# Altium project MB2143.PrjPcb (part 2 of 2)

## Sheet Arduino.SchDoc: Arduino
size A4; Date: Not used; ApprovedBy: Not used; CheckedBy: Not used; Author: Not used; CompanyName: STMicroelectronics; DrawnBy: Not used; Engineer: Not used; Organization: Not used; Address1: Not used; Address2: Not used; Address3: Not used; Address4: Not used; DocumentNumber: Not used; Revision: Not used; SheetNumber: 6; SheetTotal: 11
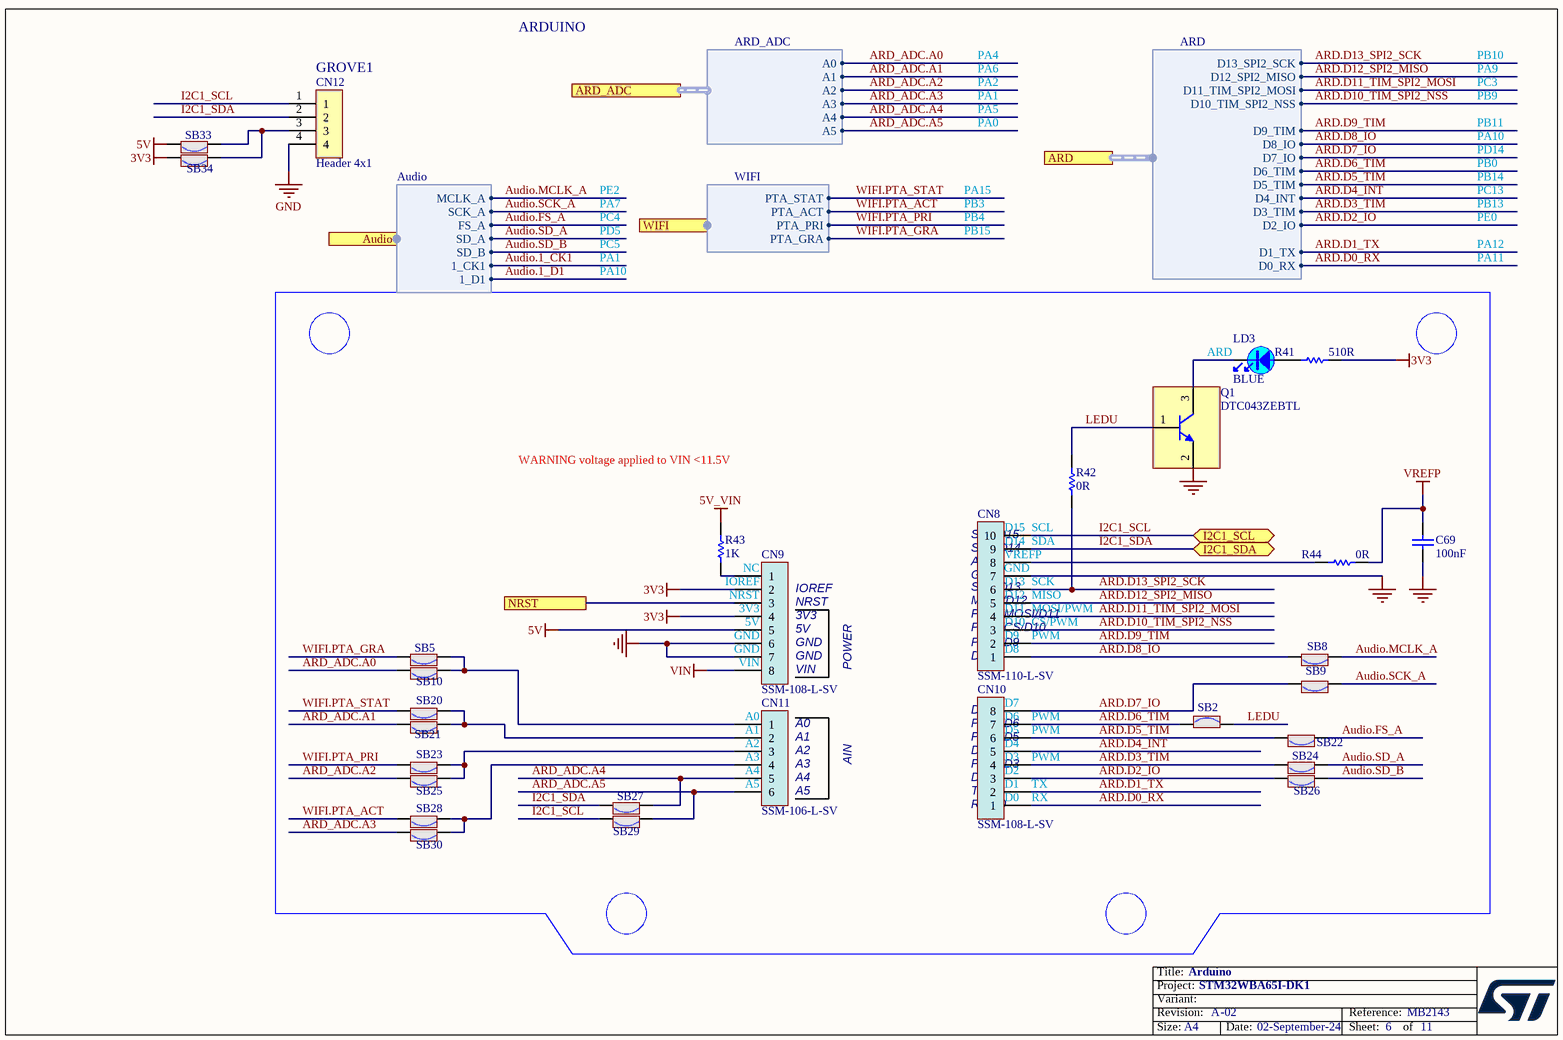
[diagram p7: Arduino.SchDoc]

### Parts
C69  value 100nF  [C0402]
CN8  value SSM-110-L-SV  [CON_SAMTEC_SSM-110-L-SV]  (hidden comment: Socket 10x1)
CN9  value SSM-108-L-SV  [CON_SAMTEC_SSM-108-L-SV]  (hidden comment: Socket 8x1)
CN10  value SSM-108-L-SV  [CON_SAMTEC_SSM-108-L-SV]  (hidden comment: Socket 8x1)
CN11  value SSM-106-L-SV  [CON_SAMTEC_SSM-106-L-SV]  (hidden comment: Socket 6x1)
CN12  Header 4x1  [CON_988-JIUBABA_A2006LF-04A]
LD3  value BLUE  [LED_0603_VISHAY_VLMB1300-GS08_BLUE_1A2K_H0P8]  (hidden comment: LED_blue)
Q1  DTC043ZEBTL  [NPN_SOT416-FL_EMT3F_1616_SC89]
R41  value 510R  [R0402]  (hidden comment: Resistor)
R42  value 0R  [R0402]
R43  value 1K  [R0402]  (hidden comment: Resistor)
R44  value 0R  [R0402]
SB2  (no value)  [SOLDER-BRIDGE_R0603-0R]
SB5  (no value)  [SOLDER-BRIDGE_R0603-0R]
SB8  (no value)  [SOLDER-BRIDGE_R0603-0R]
SB9  (no value)  [SOLDER-BRIDGE_R0603-0R]
SB10  (no value)  [SOLDER-BRIDGE_R0603-0R]
SB20  (no value)  [SOLDER-BRIDGE_R0603-0R]
SB21  (no value)  [SOLDER-BRIDGE_R0603-0R]
SB22  (no value)  [SOLDER-BRIDGE_R0603-0R]
SB23  (no value)  [SOLDER-BRIDGE_R0603-0R]
SB24  (no value)  [SOLDER-BRIDGE_R0603-0R]
SB25  (no value)  [SOLDER-BRIDGE_R0603-0R]
SB26  (no value)  [SOLDER-BRIDGE_R0603-0R]
SB27  (no value)  [SOLDER-BRIDGE_R0603-0R]
SB28  (no value)  [SOLDER-BRIDGE_R0603-0R]
SB29  (no value)  [SOLDER-BRIDGE_R0603-0R]
SB30  (no value)  [SOLDER-BRIDGE_R0603-0R]
SB33  (no value)  [SOLDER-BRIDGE_R0603-0R]
SB34  (no value)  [SOLDER-BRIDGE_R0603-0R]

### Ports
ARD (harness ARD), ARD_ADC (harness ARD_ADC), Audio (harness Audio), I2C1_SCL (bidir), I2C1_SDA (bidir), NRST, WIFI (harness WIFI)

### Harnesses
WIFI: PTA_STAT, PTA_ACT, PTA_PRI, PTA_GRA
Audio: MCLK_A, 1_CK1, FS_A, SD_A, SCK_A, SD_B, 1_D1
ARD_ADC: A0, A1, A2, A3, A4, A5
ARD: D0_RX, D1_TX, D2_IO, D3_TIM, D4_INT, D5_TIM, D6_TIM, D7_IO, D8_IO, D9_TIM, D10_TIM_SPI2_NSS, D11_TIM_SPI2_MOSI, D12_SPI2_MISO, D13_SPI2_SCK

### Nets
3V3: CN9.2 CN9.4 R41.1 SB34.2
5V: CN9.5 SB33.2
5V_VIN: R43.2
GND: C69.2 CN8.7 CN9.6 CN9.7 CN12.4 Q1.2(E)
VIN: CN9.8
VREFP: C69.1 R44.2  [project net VBAT]
ARD.D0_RX: CN10.1 ; port ARD.D0_RX
ARD.D1_TX: CN10.2 ; port ARD.D1_TX
ARD.D2_IO: CN10.3 SB26.2 ; port ARD.D2_IO
ARD.D3_TIM: CN10.4 SB24.2 ; port ARD.D3_TIM
ARD.D4_INT: CN10.5 ; port ARD.D4_INT
ARD.D5_TIM: CN10.6 SB22.2 ; port ARD.D5_TIM
ARD.D6_TIM: CN10.7 SB2.1 ; port ARD.D6_TIM
ARD.D7_IO: CN10.8 SB9.2 ; port ARD.D7_IO
ARD.D8_IO: CN8.1 SB8.2 ; port Audio.1_D1, port ARD.D8_IO  [also labelled Audio.1_D1]
ARD.D9_TIM: CN8.2 ; port ARD.D9_TIM
ARD.D10_TIM_SPI2_NSS: CN8.3 ; port ARD.D10_TIM_SPI2_NSS
ARD.D11_TIM_SPI2_MOSI: CN8.4 ; port ARD.D11_TIM_SPI2_MOSI
ARD.D12_SPI2_MISO: CN8.5 ; port ARD.D12_SPI2_MISO
ARD.D13_SPI2_SCK: CN8.6 R42.1 ; port ARD.D13_SPI2_SCK
ARD_ADC.A0: SB10.2 ; port ARD_ADC.A0
ARD_ADC.A1: SB21.2 ; port ARD_ADC.A1
ARD_ADC.A2: SB25.2 ; port ARD_ADC.A2
ARD_ADC.A3: SB30.2 ; port Audio.1_CK1, port ARD_ADC.A3  [also labelled Audio.1_CK1]
ARD_ADC.A4: CN11.5 SB27.1 ; port ARD_ADC.A4
ARD_ADC.A5: CN11.6 SB29.1 ; port ARD_ADC.A5
Audio.FS_A: SB22.1 ; port Audio.FS_A
Audio.MCLK_A: SB8.1 ; port Audio.MCLK_A
Audio.SCK_A: SB9.1 ; port Audio.SCK_A
Audio.SD_A: SB24.1 ; port Audio.SD_A
Audio.SD_B: SB26.1 ; port Audio.SD_B
I2C1_SCL: CN8.10 CN12.1 SB29.2 ; port I2C1_SCL
I2C1_SDA: CN8.9 CN12.2 SB27.2 ; port I2C1_SDA
LEDU: Q1.1(B) R42.2 SB2.2
NRST: CN9.3 ; port NRST
WIFI.PTA_ACT: SB28.2 ; port WIFI.PTA_ACT  [project net MCU.SWO]
WIFI.PTA_GRA: SB5.2 ; port WIFI.PTA_GRA
WIFI.PTA_PRI: SB23.2 ; port WIFI.PTA_PRI
WIFI.PTA_STAT: SB20.2 ; port WIFI.PTA_STAT
NetCN8_8: CN8.8 R44.1
NetCN9_1: CN9.1 R43.1
NetCN11_1: CN11.1 SB5.1 SB10.1
NetCN11_2: CN11.2 SB20.1 SB21.1
NetCN11_3: CN11.3 SB23.1 SB25.1
NetCN11_4: CN11.4 SB28.1 SB30.1
NetCN12_3: CN12.3 SB33.1 SB34.1
NetLD3_1: LD3.1 R41.2
NetLD3_2: LD3.2 Q1.3(C)

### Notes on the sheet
- ARDUINO
- (near CN12) GROVE1
- PA4
- PA6
- PA1
- PA2
- PA5
- PB9
- PB10
- PA9
- PC3
- PA0
- PA10
- PD14
- PB0
- PB11
- PB14
- PC5
- PC4
- PD5
- PE2
- PA7
- PA15
- PB4
- PB3
- PB15
- PC13
- PB13
- PE0
- PA12
- PA11
- (near LD3) ARD
- WARNING voltage applied to VIN <11.5V
- (near CN9) NC
- (near CN9) IOREF
- (near CN8) SDA/D14
- (near CN8) SCL/D15
- (near CN8) SCK/D13
- (near CN8) AVDD
- (near CN8) GND
- (near CN8) VREFP
- (near CN8) D13
- (near CN8) D14
- (near CN8) D15
- SCL
- (near CN8) SDA
- (near CN8) SCK
- (near CN9) NRST
- (near CN9) 3V3
- (near CN9) 5V
- (near CN9) GND
- (near CN8) D8
- (near CN8) PWM/D9
- (near CN8) PWM/CS/D10
- (near CN8) MISO/D12
- (near CN8) PWM/MOSI/D11
- (near CN8) D9
- (near CN8) D10
- (near CN8) D11
- (near CN8) D12
- (near CN8) MISO
- (near CN8) MOSI/PWM
- (near CN8) CS/PWM
- (near CN8) PWM
- (near CN9) VIN
- (near CN11) A0
- POWER
- (near CN10) D7
- (near CN10) D6
- (near CN10) PWM
- (near CN11) A1
- (near CN11) A2
- (near CN11) A3
- (near CN11) A4
- (near CN11) A5
- AIN
- (near CN10) TX/D1
- (near CN10) D2
- (near CN10) D4
- (near CN10) PWM/D3
- (near CN10) PWM/D5
- (near CN10) PWM/D6
- (near CN10) D5
- (near CN10) D3
- (near CN10) D1
- (near CN10) TX
- (near CN10) RX/D0
- (near CN10) D0
- (near CN10) RX

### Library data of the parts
C69 = MCD-00006: Capacitor,100nF,16V,X7R,10%,0402; Manufacturer_Part_Number: CC0402KRX7R7BB104; Manufacturer: YAGEO; Provided_By: Subcon; Initial_Board_Reference: mb1274
CN8 = MCD-02342: Socket, 10x1, 2.54mm, VR, SMT, Height 7.37mm; Part_Type: Connector; Part_Preference: Recommended; Manufacturer: SAMTEC; Order_Code_RS: 765-5420
CN9 CN10 = MCD-02345: Socket, 8x1, 2.54mm, VR, SMT, Height 7.37mm; Part_Type: Connector; Part_Preference: Recommended; Manufacturer: SAMTEC; Order_Code_RS: 765-5411
CN11 = MCD-02346: Socket, 6x1, 2.54mm, VR, SMT, Height 7.37mm; Part_Type: Connector; Part_Preference: Recommended; Manufacturer: SAMTEC; Order_Code_RS: 765-5408
CN12 = MCD-03083: GROVE female header, SMD, 4 POS, 2.0mm; Part_Type: Connector; Part_Preference: Recommended; Manufacturer: SEEED TECHNOLOGY; Manufacturer_Part_Number: 114020161; Partial_Alternate_Internal_Part_Number: MCD-01741; Order_Code_RS: NA; ShowFields: YES; ID: 5199
LD3 = MCD-00584: LED Blue, 0603 SMD, 3.3 V Forward Voltage; Part_Type: Display; Part_Preference: Recommended; Manufacturer: VISHAY; Manufacturer_Part_Number: VLMB1300-GS08; Order_Code_RS: 7730430; Component_Country_Of_Origin: China; ShowFields: YES; ID: 3160
Q1 = MCD-00280: Buffer transistor; Part_Type: IC; Manufacturer: ROHM; Provided_By: Subcon; Initial_Board_Reference: MB1329
R41 = MCD-00064: Resistor,510R,0402,1%,1/16W; Manufacturer_Part_Number: RC0402FR-07510RL; Manufacturer: YAGEO; Provided_By: Subcon; Initial_Board_Reference: MB1274
R42 R44 = MCD-00052: Resistor,0R,0402,5%,1/16W; Manufacturer_Part_Number: RC0402JR-070RL; Manufacturer: YAGEO; Provided_By: Subcon; Initial_Board_Reference: mb1274
R43 = MCD-00061: Resistor,1K,0402,1%,1/16W; Manufacturer_Part_Number: RC0402FR-071KL; Manufacturer: YAGEO; Provided_By: Subcon; Initial_Board_Reference: mb1274
SB2 SB5 SB8-SB10 SB20-SB30 SB33 SB34 = MCD-00071: Solder Bridge ON; Part_Type: Mechanical; Provided_By: Subcon; Initial_Board_Reference: mb1274

## Sheet USB_Joystick_Reset.SchDoc: MCU CLOCK & RESET
size A4; Date: Not used; ApprovedBy: Not used; CheckedBy: Not used; Author: Not used; CompanyName: STMicroelectronics; DrawnBy: Not used; Engineer: Not used; Organization: Not used; Address1: Not used; Address2: Not used; Address3: Not used; Address4: Not used; DocumentNumber: Not used; Revision: Not used; SheetNumber: 4; SheetTotal: 11
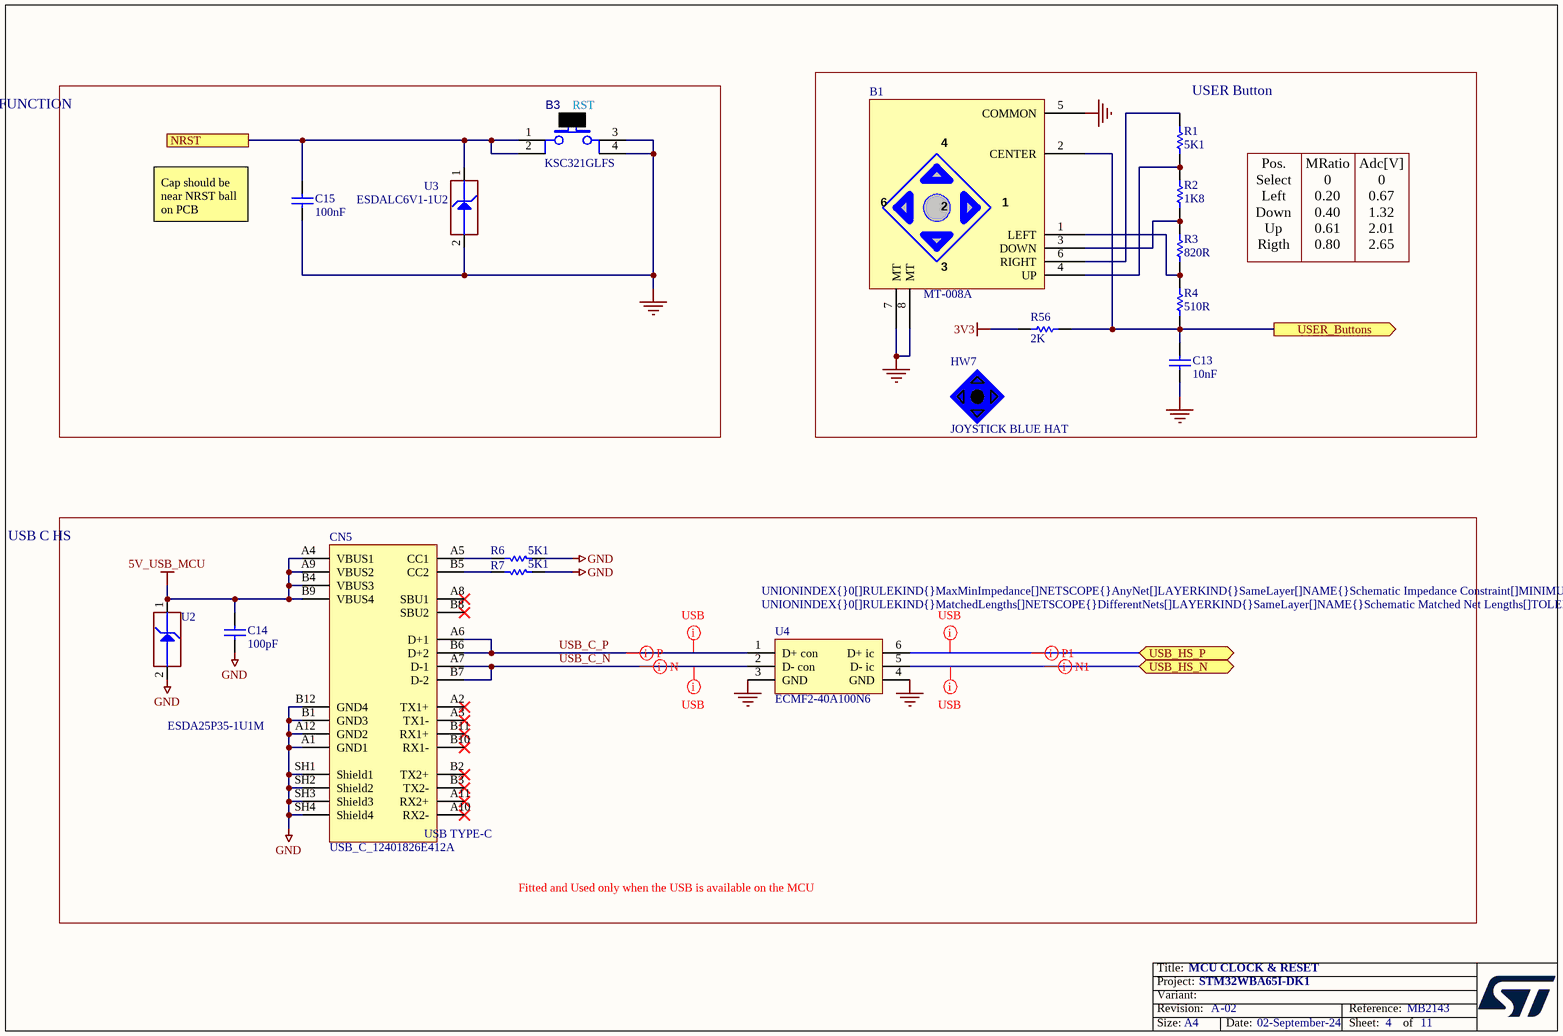
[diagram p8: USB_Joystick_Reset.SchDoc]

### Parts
B1  value MT-008A  [SWI_XIEJIA_MT-008A_6P]  (hidden comment: Joystick MT-008A_M)
B3  value KSC321GLFS  [SWI_C&K_KSC321GLFS_BLACK]  (hidden comment: SW_BLACK_KSC321GLFS)
C13  value 10nF  [C0402]  (hidden comment: Capacitor)
C14  value 100pF  [C0402]  (hidden comment: Capacitor)
C15  value 100nF  [C0402]  (hidden comment: Capacitor)
CN5  value USB_C_12401826E412A  [CON_USB-TYPEC_AMPHENOL_12401826E412A]  (hidden comment: USB_TYPE_C_Receptacle)
HW7  value JOYSTICK BLUE HAT  (hidden comment: JOYSTICK_BLUE_HAT)  (mechanical)
R1  value 5K1  [R0402]  (hidden comment: Resistor)
R2  value 1K8  [R0402]  (hidden comment: Resistor)
R3  value 820R  [R0402]  (hidden comment: Resistor)
R4  value 510R  [R0402]  (hidden comment: Resistor)
R6  value 5K1  [R0402]  (hidden comment: Resistor)
R7  value 5K1  [R0402]  (hidden comment: Resistor)
R56  value 2K  [R0402]  (hidden comment: Resistor)
U2  value ESDA25P35-1U1M  [ESD_QFN1610_2N_1K_2A]  (hidden comment: ESD-TRANSIL)
U3  value ESDALC6V1-1U2  [ESD_ST0201]
U4  ECMF2-40A100N6  [ESD_UQFN-6L_1P45X1P4_P040]

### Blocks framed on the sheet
RESET FUNCTION: B3 C15 U3
USER Button: B1 C13 HW7 R1-R4 R56
USB C HS: C14 CN5 R6 R7 U2 U4

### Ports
NRST, USB_HS_N (bidir), USB_HS_P (bidir), USER_Buttons (out)

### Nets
3V3: R56.1
5V_USB_MCU: C14.2 CN5.A4(VBUS1) CN5.A9(VBUS2) CN5.B4(VBUS3) CN5.B9(VBUS4) U2.1(IO1)
GND: B1.5(COMMON) B1.7(MT) B1.8(MT) B3.3 B3.4 C13.1 C14.1 C15.1 CN5.A1(GND1) CN5.A12(GND2) CN5.B1(GND3) CN5.B12(GND4) CN5.SH1(Shield1) CN5.SH2(Shield2) CN5.SH3(Shield3) CN5.SH4(Shield4) R6.1 R7.1 U2.2(GND) U3.2(GND) U4.3(GND) U4.4(GND)
NRST: B3.1 B3.2 C15.2 U3.1(IO1) ; port NRST
USB_C_N: CN5.A7(D-1) CN5.B7(D-2) U4.2(D-_con)
USB_C_P: CN5.A6(D+1) CN5.B6(D+2) U4.1(D+_con)
USB_HS_N: U4.5(D-_ic) ; port USB_HS_N
USB_HS_P: U4.6(D+_ic) ; port USB_HS_P
NetB1_1: B1.1(LEFT) R3.1 R4.2
NetB1_2: B1.2(CENTER) C13.2 R4.1 R56.2 ; port USER_Buttons
NetB1_3: B1.3(DOWN) R2.1 R3.2
NetB1_4: B1.4(UP) R1.1 R2.2
NetB1_6: B1.6(RIGHT) R1.2
NetCN5_A5: CN5.A5(CC1) R6.2
NetCN5_B5: CN5.B5(CC2) R7.2

Not connected (* = marked no-connect by the designer): CN5 A2(TX1+)* A3(TX1-)* A8(SBU1)* A10(RX2-)* A11(RX2+)* B2(TX2+)* B3(TX2-)* B8(SBU2)* B10(RX1-)* B11(RX1+)*

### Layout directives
rule Undefined; rule Matched Net Lengths [Tolerance = 2mm]; rule Impedance Constraint [Min = 85.00    Max = 95.00    ]: USB_C_N, USB_C_P, USB_HS_N, USB_HS_P
differential pair: USB_C_N, USB_C_P, USB_HS_N, USB_HS_P

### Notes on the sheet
- (near B3) RST
- Cap should be near NRST ball on PCB
- Pos.
  Select
  Left
  Down
  Up
  Rigth
- MRatio
  0
  0.20
  0.40
  0.61
  0.80
- Adc[V]
  0
  0.67
  1.32
  2.01
  2.65
- Fitted and Used only when the USB is available on the MCU

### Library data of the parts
B1 = MCD-00132: Joystick, 4 dir, 1 OK; BMS_Part_Number: 9180124; Part_Preference: Recommended; Part_Type: Misc; Manufacturer: XIEJIA ELECTRONICS
B3 = MCD-00175: Switch HW BLACK High3.5mm 2Newtons; Part_Type: Misc; Manufacturer: C&K; Provided_By: SUBCO; Initial_Board_Reference: MB1274
C13 = MCD-00011: Capacitor, MLCC, 10nF, 16V, X7R, +/-10%, 0402, T=0.5mm; Manufacturer_Part_Number: CC0402KRX7R7BB103; Manufacturer: YAGEO; Part_Preference: Recommended; Provided_By: SUBCO; ECCN_US: EAR99; ECCN_EU: NEC; Order_Code_RS: 669-8688
C14 = MCD-00205: Capacitor, MLCC, 100pF, 50V, NPO, +/-5%, 0402, T=0.5mm; Manufacturer_Part_Number: CC0402JRNPO9BN101; Manufacturer: YAGEO; Part_Preference: Recommended; Component_Country_Of_Origin: China
C15 = MCD-00006: Capacitor, MLCC, 100nF, 16V, X7R, 10%, 0402, T=0.5mm; Manufacturer_Part_Number: CC0402KRX7R7BB104; Manufacturer: YAGEO; Provided_By: SUBCO; Initial_Board_Reference: MB1274
CN5 = MCD-03232: USB_TypeC, 24 pins, RA, SMD, T=2.96mm; Part_Type: Connector; Part_Preference: Recommended; Manufacturer: AMPHENOL ICC; Manufacturer_Part_Number: 12401826E412A; Component_Country_Of_Origin: China°; ShowFields: YES; ID: 5348
HW7 = MCD-01337: Joystick Blue Hat; Part_Type: Misc; Part_Preference: Alternate; Manufacturer: JIUBABA; Manufacturer_Part_Number: PB-504; Component_Country_Of_Origin: Unknown; Alternate_EMS: A; ShowFields: YES; ID: 3437
R1 = MCD-00333: Resistor, 5K1, 0402, +/-1%, 1/16W; Manufacturer_Part_Number: RC0402FR-075K1L; Manufacturer: YAGEO; Part_Preference: Recommended; ECCN_US: EAR99; ECCN_EU: NEC; Provided_By: SUBCO
R2 = MCD-00409: Resistor, 1K8, 0402, +/-1%, 1/16W; Manufacturer_Part_Number: RC0402FR-071K8L; Manufacturer: YAGEO; Part_Preference: Recommended; ECCN_US: EAR99; ECCN_EU: NEC; Provided_By: SUBCO
R3 = MCD-00527: Resistor, 820R, 0402, +/-1%, 1/16W; Manufacturer_Part_Number: RC0402FR-07820RL; Manufacturer: YAGEO; Part_Preference: Recommended; ECCN_US: EAR99; ECCN_EU: NEC; Provided_By: SUBCO
R4 = MCD-00064: Resistor, 510R, 0402, +/-1%, 1/16W; Manufacturer_Part_Number: RC0402FR-07510RL; Manufacturer: YAGEO; Part_Preference: Recommended; ECCN_US: EAR99; ECCN_EU: NEC; Provided_By: SUBCO
R6 R7 = MCD-00333: Resistor, 5K1, 0402, +/-1%, 1/16W; Manufacturer_Part_Number: RC0402FR-075K1L; Manufacturer: YAGEO; Part_Preference: Recommended; Component_Country_Of_Origin: China
R56 = MCD-00419: Resistor, 2K, 0402, +/-1%, 1/16W; Manufacturer_Part_Number: RC0402FR-072KL; Manufacturer: YAGEO; Part_Preference: Recommended; ECCN_US: EAR99; ECCN_EU: NEC; Provided_By: SUBCO
U2 = MCD-01207: High power Transient voltage suppressor:25V/35A EOS and ESD transients protection.; Part_Type: Diode; Manufacturer: STMICROELECTRONICS; BMS_Part_Number: 9179045; Part_Preference: Recommended; Manufacturer_HQ_COO: EU; Component_Country_Of_Origin: China
U3 = MCD-00170: ESD protection 6V1; Part_Type: Diode; Manufacturer: STMICROELECTRONICS; ECCN_US: EAR99; ECCN_EU: NEC; Provided_By: Subcon; Initial_Board_Reference: MB1274
U4 = MCD-03060: IC, ESD protection and Common Filter High Speed serial Interfaces, 10.7 GHz; Part_Preference: Recommended; Manufacturer: STMICROELECTRONICS; Component_Country_Of_Origin: China; ShowFields: YES; ID: 5176

## Sheet Audio_Codec.SchDoc: Audio_Codec
size A4; Date: Not used; ApprovedBy: Not used; CheckedBy: Not used; Author: Not used; CompanyName: STMicroelectronics; DrawnBy: Not used; Engineer: Not used; Organization: Not used; Address1: Not used; Address2: Not used; Address3: Not used; Address4: Not used; DocumentNumber: Not used; Revision: Not used; SheetNumber: 5; SheetTotal: 11
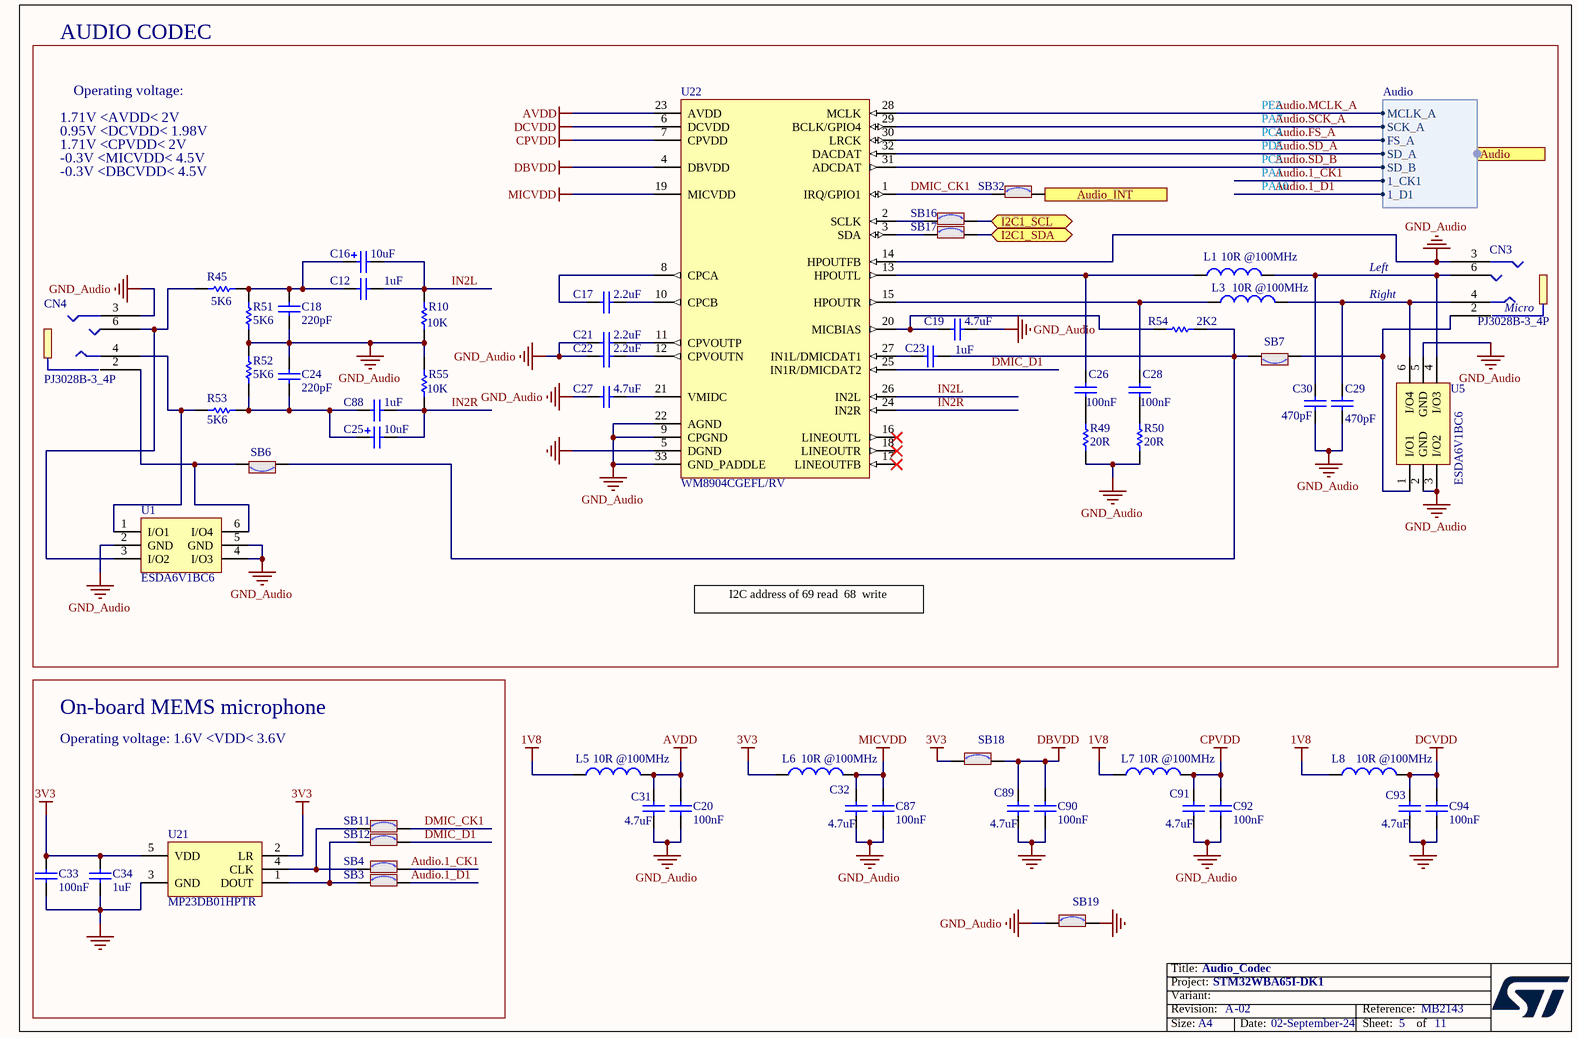
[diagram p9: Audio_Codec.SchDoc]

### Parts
C12  value 1uF  [C0402]  (hidden comment: Capacitor)
C16  value 10uF  [C6032-28_VISHAY_293D-Case-C]  (hidden comment: Cap_POL_TANA)
C17  value 2.2uF  [C0603]  (hidden comment: Capacitor)
C18  value 220pF  [C0402]  (hidden comment: Capacitor)
C19  value 4.7uF  [C0603]  (hidden comment: Capacitor)
C20  value 100nF  [C0402]  (hidden comment: Capacitor)
C21  value 2.2uF  [C0603]  (hidden comment: Capacitor)
C22  value 2.2uF  [C0603]  (hidden comment: Capacitor)
C23  value 1uF  [C0402]  (hidden comment: Capacitor)
C24  value 220pF  [C0402]  (hidden comment: Capacitor)
C25  value 10uF  [C6032-28_VISHAY_293D-Case-C]  (hidden comment: Cap_POL_TANA)
C26  value 100nF  [C0402]  (hidden comment: Capacitor)
C27  value 4.7uF  [C0603]  (hidden comment: Capacitor)
C28  value 100nF  [C0402]  (hidden comment: Capacitor)
C29  value 470pF  [C0402]  (hidden comment: Capacitor)
C30  value 470pF  [C0402]  (hidden comment: Capacitor)
C31  value 4.7uF  [C0603]  (hidden comment: Capacitor)
C32  value 4.7uF  [C0603]  (hidden comment: Capacitor)
C33  value 100nF  [C0402]  (hidden comment: Capacitor)
C34  value 1uF  [C0402]  (hidden comment: Capacitor)
C87  value 100nF  [C0402]  (hidden comment: Capacitor)
C88  value 1uF  [C0402]  (hidden comment: Capacitor)
C89  value 4.7uF  [C0603]  (hidden comment: Capacitor)
C90  value 100nF  [C0402]  (hidden comment: Capacitor)
C91  value 4.7uF  [C0603]  (hidden comment: Capacitor)
C92  value 100nF  [C0402]  (hidden comment: Capacitor)
C93  value 4.7uF  [C0603]  (hidden comment: Capacitor)
C94  value 100nF  [C0402]  (hidden comment: Capacitor)
CN3  value PJ3028B-3_4P  [CON_PHONE-JACK-3P5_HY_PJ3028B]  (hidden comment: Jack_PJ3028B-3_4P)
CN4  value PJ3028B-3_4P  [CON_PHONE-JACK-3P5_HY_PJ3028B]  (hidden comment: Jack_PJ3028B-3_4P)
L1  value 10R @100MHz  [IND_0402_MURATA_BLM15H_H0P5]  (hidden comment: Inductor)
L3  value 10R @100MHz  [IND_0402_MURATA_BLM15H_H0P5]  (hidden comment: Inductor)
L5  value 10R @100MHz  [IND_0402_MURATA_BLM15H_H0P5]  (hidden comment: Inductor)
L6  value 10R @100MHz  [IND_0402_MURATA_BLM15H_H0P5]  (hidden comment: Inductor)
L7  value 10R @100MHz  [IND_0402_MURATA_BLM15H_H0P5]  (hidden comment: Inductor)
L8  value 10R @100MHz  [IND_0402_MURATA_BLM15H_H0P5]  (hidden comment: Inductor)
R10  value 10K  [R0402]  (hidden comment: Resistor)
R45  value 5K6  [R0402]  (hidden comment: Resistor)
R49  value 20R  [R0603]  (hidden comment: Resistor)
R50  value 20R  [R0603]  (hidden comment: Resistor)
R51  value 5K6  [R0402]  (hidden comment: Resistor)
R52  value 5K6  [R0402]  (hidden comment: Resistor)
R53  value 5K6  [R0402]  (hidden comment: Resistor)
R54  value 2K2  [R0402]  (hidden comment: Resistor)
R55  value 10K  [R0402]  (hidden comment: Resistor)
SB3  (no value)  [SOLDER-BRIDGE_R0603-0R]
SB4  (no value)  [SOLDER-BRIDGE_R0603-0R]
SB6  (no value)  [SOLDER-BRIDGE_R0603-0R]
SB7  (no value)  [SOLDER-BRIDGE_R0603-0R]
SB11  (no value)  [SOLDER-BRIDGE_R0603-0R]
SB12  (no value)  [SOLDER-BRIDGE_R0603-0R]
SB16  (no value)  [SOLDER-BRIDGE_R0603-0R]
SB17  (no value)  [SOLDER-BRIDGE_R0603-0R]
SB18  (no value)  [SOLDER-BRIDGE_R0603-0R]
SB19  (no value)  [SOLDER-BRIDGE_R0603-0R]
SB32  (no value)  [SOLDER-BRIDGE_R0603-0R]
U1  ESDA6V1BC6  [ESD_SOT23-6L]
U5  ESDA6V1BC6  [ESD_SOT23-6L]
U21  value MP23DB01HPTR  [MIC_STM_MP23DB01MMTR]  (hidden comment: MP23DB01MMTR)
U22  WM8904CGEFL/RV  [ICC_QFN32-EPAD_4X4_P040]

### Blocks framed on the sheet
AUDIO CODEC: C12 C16-C19 C21-C30 C88 CN3 CN4 L1 L3 R10 R45 R49-R55 SB6 SB7 SB16 SB17 SB32 U1 U5 U22
On-board MEMS microphone: C33 C34 SB3 SB4 SB11 SB12 U21

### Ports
Audio (harness Audio), Audio_INT (out), I2C1_SCL (bidir), I2C1_SDA (bidir)

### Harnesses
Audio: MCLK_A, 1_CK1, FS_A, SD_A, SCK_A, SD_B, 1_D1

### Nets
1V8: L5.1 L7.1 L8.1
3V3: C33.2 C34.1 L6.1 SB18.1 U21.2(LR) U21.5(VDD)
AVDD: C20.2 C31.2 L5.2 U22.23(AVDD)
CPVDD: C91.2 C92.2 L7.2 U22.7(CPVDD)
DBVDD: C89.2 C90.2 SB18.2 U22.4(DBVDD)
DCVDD: C93.2 C94.2 L8.2 U22.6(DCVDD)
GND: C33.1 C34.2 C89.1 C90.1 C93.1 C94.1 SB19.2 U21.3(GND) U22.5(DGND)
GND_Audio: C18.1 C19.2 C20.1 C21.2 C22.2 C24.2 C27.1 C29.1 C30.1 C31.1 C32.1 C87.1 C91.1 C92.1 CN3.3 CN4.3 R10.2 R49.1 R50.1 R51.1 R52.2 R55.1 SB19.1 U1.2(GND) U1.4(I/O3) U1.5(GND) U5.2(GND) U5.3(I/O2) U5.5(GND) U22.9(CPGND) U22.14(HPOUTFB) U22.22(AGND) U22.33(GND_PADDLE)
MICVDD: C32.2 C87.2 L6.2 U22.19(MICVDD)
Audio.1_CK1: SB4.2 ; port Audio.1_CK1  [project net ARD_ADC.A3]
Audio.1_D1: SB3.2 ; port Audio.1_D1  [project net ARD.D8_IO]
Audio.FS_A: U22.30(LRCK) ; port Audio.FS_A
Audio.MCLK_A: U22.28(MCLK) ; port Audio.MCLK_A
Audio.SCK_A: U22.29(BCLK/GPIO4) ; port Audio.SCK_A
Audio.SD_A: U22.32(DACDAT) ; port Audio.SD_A
Audio.SD_B: U22.31(ADCDAT) ; port Audio.SD_B
DMIC_CK1: SB11.2 SB32.1 U22.1(IRQ/GPIO1)
DMIC_D1: SB12.2 U22.25(IN1R/DMICDAT2)
I2C1_SCL: SB16.2 ; port I2C1_SCL
I2C1_SDA: SB17.2 ; port I2C1_SDA
IN2L: C12.2 C16.2 R10.1 U22.26(IN2L)
IN2R: C25.2 C88.2 R55.2 U22.24(IN2R)
NetC12_1: C12.1 C16.1 C18.2 R45.2 R51.2
NetC17_1: C17.1 U22.10(CPCB)
NetC17_2: C17.2 U22.8(CPCA)
NetC19_1: C19.1 R54.2 U22.20(MICBIAS)
NetC21_1: C21.1 U22.11(CPVOUTP)
NetC22_1: C22.1 U22.12(CPVOUTN)
NetC23_1: C23.1 U22.27(IN1L/DMICDAT1)
NetC23_2: C23.2 R54.1 SB6.1 SB7.2
NetC24_1: C24.1 C25.1 C88.1 R52.1 R53.2
NetC26_1: C26.1 L1.1 U22.13(HPOUTL)
NetC26_2: C26.2 R49.2
NetC27_2: C27.2 U22.21(VMIDC)
NetC28_1: C28.1 L3.1 U22.15(HPOUTR)
NetC28_2: C28.2 R50.2
NetC29_2: C29.2 CN3.4 L3.2 U5.6(I/O4)
NetC30_2: C30.2 CN3.6 L1.2 U5.4(I/O3)
NetCN3_2: CN3.2 SB7.1 U5.1(I/O1)
NetCN4_2: CN4.2 SB6.2 U1.6(I/O4)
NetCN4_4: CN4.4 R53.1 U1.1(I/O1)
NetCN4_6: CN4.6 R45.1 U1.3(I/O2)
NetSB3_1: SB3.1 SB12.1 U21.1(DOUT)
NetSB4_1: SB4.1 SB11.1 U21.4(CLK)
NetSB16_1: SB16.1 U22.2(SCLK)
NetSB17_1: SB17.1 U22.3(SDA)
NetSB32_2: SB32.2 ; port Audio_INT

Not connected (* = marked no-connect by the designer): U22 16(LINEOUTL)* 17(LINEOUTFB)* 18(LINEOUTR)*

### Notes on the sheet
- Operating voltage:
- PE2
- 1.71V <AVDD< 2V
- 0.95V <DCVDD< 1.98V
- 1.71V <CPVDD< 2V
- -0.3V <MICVDD< 4.5V
- -0.3V <DBCVDD< 4.5V
- PC5
- PC4
- PD5
- PA7
- PA1
- PA10
- Left
- Right
- (near CN3) Micro
- I2C address of 69 read  68  write
- Operating voltage: 1.6V <VDD< 3.6V

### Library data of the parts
C12 C23 C88 = MCD-00095: Capacitor, MLCC, 1uF, 25V, X5R, +/-10%, 0402, T=0,5mm; Part_Preference: Recommended; Manufacturer: MURATA; Manufacturer_Part_Number: GRM155R61E105KA12; Alternate_Manufacturer_Part_Number: GRM155R60J105KE19; Order_Code_RS: 846-7287
C16 C25 = MCD-03891: Capacitor, Tantalum, 10uF, 16V, 1.8R, +/-10%, 6032, T=2.5mm; Part_Preference: Recommended; Manufacturer: VISHAY; Manufacturer_Part_Number: 293D106X9016C2TE3; Component_Country_Of_Origin: China, Israel; ShowFields: YES; ID: 6007
C17 C21 C22 = MCD-00012: Capacitor, MLCC, 2.2uF, 10V, X5R, +/- 10%, 0603, T=0.8mm; BMS_Part_Number: 9142010; Part_Preference: Recommended; Manufacturer: YAGEO; Manufacturer_Part_Number: CC0603KRX5R6BB225; Component_Country_Of_Origin: China; ShowFields: YES; ID: 2467
C18 C24 = MCD-01225: Capacitor, MLCC, 220pF, 50V, NPO, +/-5%, 0402, T=0.5mm; Part_Preference: Recommended; Manufacturer: YAGEO; Manufacturer_Part_Number: CC0402JRNPO9BN221; Order_Code_RS: 616-9284; Component_Country_Of_Origin: China; ShowFields: YES; ID: 3272
C19 C27 C31 C32 C89 C91 C93 = MCD-00009: Capacitor, MLCC, 4.7uF, 16V, X5R, +/-10%, 0603, T=0.8mm; Part_Preference: Recommended; Manufacturer: YAGEO; Manufacturer_Part_Number: CC0603KRX5R7BB475; Partial_Alternate_Internal_Part_Number: MCD-03565; Component_Country_Of_Origin: China; Alternate_EMS: A; ShowFields: YES; ID: 2471
C20 C33 C87 C90 C92 C94 = MCD-00006: Capacitor, MLCC, 100nF, 16V, X7R, +/-10%, 0402, T=0.5mm; Part_Preference: Recommended; Manufacturer: YAGEO; Manufacturer_Part_Number: CC0402KRX7R7BB104; Partial_Alternate_Internal_Part_Number: MCD-03299; Order_Code_RS: 9402047; Component_Country_Of_Origin: China; ShowFields: YES; ID: 2474
C26 C28 = MCD-00006: Capacitor, MLCC, 100nF, 16V, X7R, +/-10%, 0402, T=0.5mm; Manufacturer_Part_Number: CC0402KRX7R7BB104; Manufacturer: YAGEO; Part_Preference: Recommended; Partial_Alternate_Internal_Part_Number: MCD-03299; Order_Code_RS: 616-9701; Component_Country_Of_Origin: China; ShowFields: YES; ID: 2474; Alternate_EMS: M
C29 C30 = MCD-00724: Capacitor, MLCC, 470pF, 50V, NPO, +/-5%, 0402, T=0.5mm; Part_Preference: Recommended; Manufacturer: YAGEO; Manufacturer_Part_Number: CC0402JRNPO9BN471; Order_Code_RS: 199-2186; Component_Country_Of_Origin: China; ShowFields: YES; ID: 3023
C34 = MCD-01722: Capacitor, 1uF, 10V, X5R, 10%, 0402, T=0.5mm; Manufacturer_Part_Number: CC0402KRX5R6BB105; Manufacturer: YAGEO; Provided_By: SUBCO
CN3 CN4 = MCD-00263: Connector Jack Socket Stereo 3.5mm, 4 pins, RA, SMT, Black; Part_Preference: Recommended; Manufacturer: QIAOD
L1 L3 L5-L8 = MCD-02381: Ferrite bead, 10R @100MHz, 5R, 0.75A, 0.07R, 0402, T=0.22mm; Part_Preference: Recommended; Manufacturer: MURATA; Manufacturer_Part_Number: BLM02AX100SN1D; Component_Country_Of_Origin: Japan; ShowFields: YES; ID: 4487
R10 R55 = MCD-00053: Resistor,10K,0402,1%,1/16W; Manufacturer_Part_Number: RC0402FR-0710KL; Manufacturer: YAGEO; Provided_By: SUBCO
R45 R51-R53 = MCD-00491: Resistor, 5K6, 0402, +/-1%, 1/16W; BMS_Part_Number: 9131160; Part_Preference: Recommended; Manufacturer: YAGEO; Manufacturer_Part_Number: RC0402FR-075K6L; Component_Country_Of_Origin: China; ShowFields: YES; ID: 2786
R49 R50 = MCD-00345: Resistor, 20R, 0603, +/-1%, 1/10W; Part_Preference: Recommended; Manufacturer: YAGEO; Manufacturer_Part_Number: RC0603FR-0720RL; Component_Country_Of_Origin: China; ShowFields: YES; ID: 2933
R54 = MCD-00057: Resistor,2K2,0402,1%,1/16W; Part_Preference: Recommended; Manufacturer: YAGEO; Manufacturer_Part_Number: RC0402FR-072K2L
SB3 SB4 SB6 SB7 SB11 SB12 SB16-SB19 SB32 = MCD-00071: as SB2 on sheet Arduino
U1 U5 = MCD-00247: Quad Bidir ESD protection; BMS_Part_Number: 9179038; Part_Preference: Recommended; Part_Type: Diode; Manufacturer: STMICROELECTRONICS; Manufacturer_HQ_COO: EU
U21 = MCD-02122: MEMS sensors , omnidirectionnal digital microphone; Part_Preference: Recommended; Part_Type: IC; Manufacturer: STMICROELECTRONICS; Component_Country_Of_Origin: China
U22 = MCD-03825: Audio Codec, Ultra Low-Power Codec for Portable Audio Applications; Part_Type: IC; Part_Preference: Recommended; Manufacturer: CIRRUS LOGIC; ShowFields: YES; ID: 5941

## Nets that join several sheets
1V8: Board_Power (C86.2 TP2.1 U19.5), Audio_Codec (L5.1 L7.1 L8.1)
3V3: Board_Power (8 pins), External_Debug_Interface (CN14.3 CN15.1), OLED (C74.1 U13.8), STLink_V3EC (LNK1.1), MCU (5 pins), Arduino (CN9.2 CN9.4 R41.1 SB34.2), USB_Joystick_Reset (R56.1), Audio_Codec (6 pins)
3V6: Board_Power (C77.1 U16.5), OLED (C75.1 U13.5)
5V: Board_Power (12 pins), STLink_V3EC (R22.2), Arduino (CN9.5 SB33.2)
5V_STLK: Board_Power (JP4.1), STLink_V3EC (6 pins)
5V_USB_MCU: Board_Power (JP4.9), USB_Joystick_Reset (6 pins)
5V_VIN: Board_Power (C84.2 JP4.3 U20.2 U20.4), STLink_V3EC (D2.1), Arduino (R43.2)
GND: Board_Power (17 pins), External_Debug_Interface (7 pins), OLED (10 pins), STLink_V3EC (97 pins), MCU (36 pins), Arduino (6 pins), USB_Joystick_Reset (22 pins), Audio_Codec (9 pins)
VBAT: Board_Power (JP2.1), MCU (28 pins), Arduino (C69.1 R44.2)
VBUS_STLK: Board_Power (JP4.7), STLink_V3EC (12 pins)
VIN: Board_Power (C83.2 SB13.1 U20.3), Arduino (CN9.8)
ARD.D0_RX: MCU (CN2.45 SB42.1), Arduino (CN10.1)
ARD.D1_TX: MCU (CN2.43 SB41.1), Arduino (CN10.2)
ARD.D2_IO: OLED (U13.13), MCU (CN2.41), Arduino (CN10.3 SB26.2)
ARD.D3_TIM: MCU (CN2.39), Arduino (CN10.4 SB24.2)
ARD.D4_INT: MCU (CN2.46 SB35.2), Arduino (CN10.5)
ARD.D5_TIM: MCU (CN2.35), Arduino (CN10.6 SB22.2)
ARD.D6_TIM: MCU (CN2.29), Arduino (CN10.7 SB2.1)
ARD.D7_IO: MCU (CN2.27), Arduino (CN10.8 SB9.2)
ARD.D8_IO: MCU (CN2.25), Arduino (CN8.1 SB8.2), Audio_Codec (SB3.2)
ARD.D9_TIM: MCU (CN2.23), Arduino (CN8.2)
ARD.D10_TIM_SPI2_NSS: MCU (CN2.21), Arduino (CN8.3)
ARD.D11_TIM_SPI2_MOSI: MCU (CN2.15), Arduino (CN8.4)
ARD.D12_SPI2_MISO: MCU (CN2.13), Arduino (CN8.5)
ARD.D13_SPI2_SCK: MCU (CN2.11), Arduino (CN8.6 R42.1)
ARD_ADC.A0: MCU (CN1.24), Arduino (SB10.2)
ARD_ADC.A1: MCU (CN1.26), Arduino (SB21.2)
ARD_ADC.A2: MCU (CN1.36), Arduino (SB25.2)
ARD_ADC.A3: MCU (CN1.38 U12.2), Arduino (SB30.2), Audio_Codec (SB4.2)
ARD_ADC.A4: MCU (CN1.42), Arduino (CN11.5 SB27.1)
ARD_ADC.A5: OLED (U13.14), MCU (CN1.44 U12.6), Arduino (CN11.6 SB29.1)
Audio.FS_A: MCU (CN1.29), Arduino (SB22.1), Audio_Codec (U22.30)
Audio.MCLK_A: MCU (CN1.21), Arduino (SB8.1), Audio_Codec (U22.28)
Audio.SCK_A: MCU (CN2.28), Arduino (SB9.1), Audio_Codec (U22.29)
Audio.SD_A: MCU (CN2.5), Arduino (SB24.1), Audio_Codec (U22.32)
Audio.SD_B: MCU (CN2.40), Arduino (SB26.1), Audio_Codec (U22.31)
I2C1_SCL: MCU (CN2.7 R8.1), Arduino (CN8.10 CN12.1 SB29.2), Audio_Codec (SB16.2)
I2C1_SDA: MCU (CN2.9 R9.1), Arduino (CN8.9 CN12.2 SB27.2), Audio_Codec (SB17.2)
JNTRST: External_Debug_Interface (CN15.9 U15.4), MCU (SB31.1)
MCU.CTS: STLink_V3EC (U6.N13), MCU (SB40.1)
MCU.JTDI: External_Debug_Interface (CN14.10 CN15.8 U14.4), STLink_V3EC (R19.2), MCU (CN2.22)
MCU.RTS: STLink_V3EC (U6.N14), MCU (SB39.1)
MCU.SWCLK: External_Debug_Interface (CN14.6 CN14.9 CN15.4 U14.1), STLink_V3EC (R18.2), MCU (CN1.15)
MCU.SWDIO: External_Debug_Interface (CN14.4 CN15.2 U14.5), STLink_V3EC (R16.2), MCU (CN1.13)
MCU.SWO: External_Debug_Interface (CN14.8 CN15.6 U14.3), STLink_V3EC (R17.2), MCU (CN2.12), Arduino (SB28.2)
MCU.VCP2_RX: STLink_V3EC (R57.2), MCU (SB42.2)
MCU.VCP2_TX: STLink_V3EC (R58.2), MCU (SB41.2)
MCU.VCP_RX: External_Debug_Interface (CN14.13 U15.3), STLink_V3EC (R21.2), MCU (CN1.45)
MCU.VCP_TX: External_Debug_Interface (CN14.14 U15.1), STLink_V3EC (R20.2), MCU (CN1.47)
Mem_MOSI: OLED (U13.15), MCU (CN2.48 U12.5)
NetB1_2: MCU (CN2.37), USB_Joystick_Reset (B1.2 C13.2 R4.1 R56.2)
NetSB32_2: MCU (SB35.1), Audio_Codec (SB32.2)
NRST: External_Debug_Interface (CN14.12 CN15.10 U15.5), STLink_V3EC (R24.2), MCU (CN1.12), Arduino (CN9.3), USB_Joystick_Reset (B3.1 B3.2 C15.2 U3.1)
OLED.CS: OLED (U13.11), MCU (CN1.19)
OLED.RST: OLED (U13.12), MCU (CN1.23)
USB_HS_N: MCU (CN2.18), USB_Joystick_Reset (U4.5)
USB_HS_P: MCU (CN2.16), USB_Joystick_Reset (U4.6)
WIFI.PTA_GRA: MCU (CN2.34 SB40.2), Arduino (SB5.2)
WIFI.PTA_PRI: MCU (CN2.42 SB31.2), Arduino (SB23.2)
WIFI.PTA_STAT: MCU (CN1.8 SB39.2), Arduino (SB20.2)

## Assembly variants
WBA65I: not fitted C46 C47 CN7 CN15 JP1 R39 R40 R42 R43 R44 R59 SB1 SB3 SB4 SB5 SB6 SB8 SB9 SB13 SB15 SB20 SB22 SB23 SB24 SB26 SB27 SB28 SB29 SB31 SB33 SB35 SB37 SB39 SB40 SB41 SB42 U10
